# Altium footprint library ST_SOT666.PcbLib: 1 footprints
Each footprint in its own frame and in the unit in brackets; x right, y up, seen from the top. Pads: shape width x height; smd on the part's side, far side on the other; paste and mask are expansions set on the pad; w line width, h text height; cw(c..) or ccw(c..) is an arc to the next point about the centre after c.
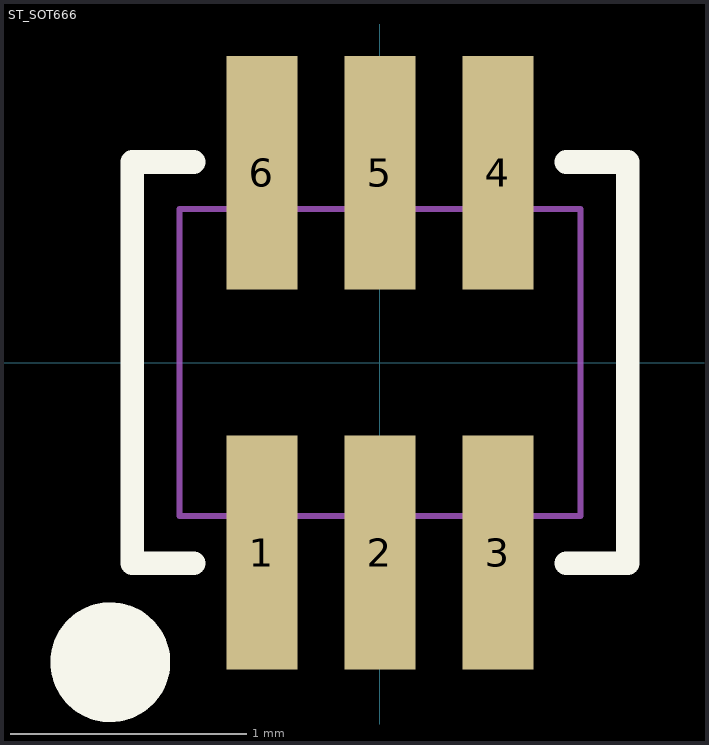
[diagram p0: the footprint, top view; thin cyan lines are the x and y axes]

## ST_SOT666 [mm] "ST_SOT666"
pads (6):
  rect 0.3x0.99 smd mask+0.025: 1(-0.5,-0.805) 2(0,-0.805) 3(0.5,-0.805) 4(0.5,0.805) 5(0,0.805) 6(-0.5,0.805)
Top Overlay:
  circle w0.254: c-1.143,-1.27 r0.127
  lines w0.1: -0.79,-0.85 -1.05,-0.85 -1.05,0.85 -0.79,0.85 ; 0.79,-0.85 1.05,-0.85 1.05,0.85 0.79,0.85
Mechanical 5:
  text "6" at -0.61,1.605 h0.3
  text "1" at -0.61,-1.905 h0.3
  text "3" at 0.39,-1.905 h0.3
  text "4" at 0.39,1.605 h0.3
  text "2" at -0.11,-1.905 h0.3
  text "5" at -0.11,1.605 h0.3
Mechanical 6:
  lines w0.025: -0.85,-0.65 0.85,-0.65 0.85,0.65 -0.85,0.65 -0.85,-0.65
Mechanical 7:
  lines w0: -0.85,-0.65 -0.85,0.65 0.85,0.65 0.85,-0.65 -0.85,-0.65
3D body: height 0.6, standoff 0, extent -0.85,-0.65 0.85,0.65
